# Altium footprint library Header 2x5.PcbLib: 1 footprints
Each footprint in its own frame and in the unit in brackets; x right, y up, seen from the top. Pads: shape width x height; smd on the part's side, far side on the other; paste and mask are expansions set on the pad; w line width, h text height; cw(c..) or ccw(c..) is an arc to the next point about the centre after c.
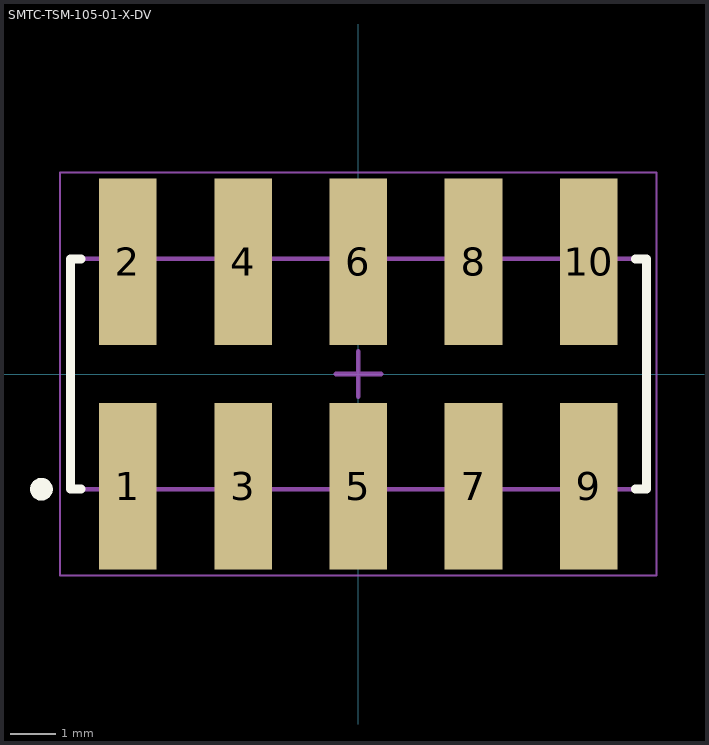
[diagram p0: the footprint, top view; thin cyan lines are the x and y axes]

## SMTC-TSM-105-01-X-DV [mm] "Double Row Gullwing ASM, 2x5 Pins, Vertical, 2.54mm Pitch, Male"
height 9.9
pads (10):
  rect 1.27x3.68 smd: 1(-5.08,-2.475) 2(-5.08,2.475) 3(-2.54,-2.475) 4(-2.54,2.475) 5(0,-2.475) 6(0,2.475) 7(2.54,-2.475) 8(2.54,2.475) 9(5.08,-2.475) 10(5.08,2.475)
Top Overlay:
  circle w0.25: c-6.985,-2.54 r0.125
  lines w0.2: -6.115,-2.54 -6.35,-2.54 -6.35,2.54 -6.115,2.54 ; 6.115,-2.54 6.35,-2.54 6.35,2.54 6.115,2.54
Mechanical 13:
  lines w0.1: -6.35,-2.54 6.35,-2.54 6.35,2.54 -6.35,2.54 -6.35,-2.54
Mechanical 15:
  lines w0.05: -6.575,-4.44 -6.575,4.44 6.575,4.44 6.575,-4.44 -6.575,-4.44
  lines w0.1: -0.5,0 0.5,0 ; 0,-0.5 0,0.5
3D body "TSM-105-01-X-DV.step": height 9.65, standoff 0, extent -6.35,-3.683 6.35,3.683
